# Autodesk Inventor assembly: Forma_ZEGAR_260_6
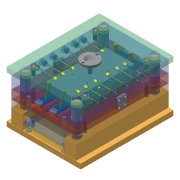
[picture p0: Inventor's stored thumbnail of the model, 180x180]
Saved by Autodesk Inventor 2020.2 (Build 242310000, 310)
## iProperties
Created: 2015-01
Part Number: Forma_ZEGAR_260_6
Document SubType Name: Assembly
Designer: F.Stasiak
Catalog Web Link: www.expertbooks.pl
Manager: www.cadconsulting.pl
Company: Fabian Stasiak CAD Consulting
Author: F.Stasiak
Subject: Zbiór ćwiczeń. Autodesk Inventor 2020. Kurs Professional
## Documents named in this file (14)
- C:\2020_Kurs_Professional\R6 Formy\Forma_ZEGAR_260_6.iam
- C:\2020_Kurs_Professional\R6 Formy\Komponenty\Forma_ZEGAR_260_6_ZEGAR_260_LY.iam
- C:\2020_Kurs_Professional\R6 Formy\Komponenty\Forma_ZEGAR_260_6_RG.ipt
- C:\2020_Kurs_Professional\R6 Formy\Komponenty\Forma_ZEGAR_260_6_CH.ipt
- C:\2020_Kurs_Professional\R6 Formy\Komponenty\MB\DME_E 1\Forma_ZEGAR_260_6_MB.iam
- C:\2020_Kurs_Professional\R6 Formy\Komponenty\Forma_ZEGAR_260_6_Combined CV1.ipt
- C:\2020_Kurs_Professional\R6 Formy\Komponenty\Forma_ZEGAR_260_6_Combined CR1.ipt
- C:\2020_Kurs_Professional\R6 Formy\Komponenty\Wypychacze\DME_AH\Grupa EP2.0\Forma_ZEGAR_260_4_Grupa EP2_EP1.ipt
- C:\2020_Kurs_Professional\R6 Formy\Komponenty\Tuleja wlewowa\DME_AGN\Forma_ZEGAR_260_4_AGN 76-3,5-0.ipt
- C:\2020_Kurs_Professional\R6 Formy\Komponenty\Pierścień centrujący\RABOURDIN_646  typ B\Forma_ZEGAR_260_4_646-90-25-12,5.ipt
- C:\2020_Kurs_Professional\R6 Formy\Komponenty\LS\DME_FW45 1\Forma_ZEGAR_260_6_LS1.iam
- C:\2020_Kurs_Professional\R6 Formy\Komponenty\Komponenty układu chłodzenia\DME_DR 1700\Forma_ZEGAR_260_4_DR 1700 8x2.ipt
- C:\2020_Kurs_Professional\R6 Formy\Komponenty\Komponenty układu chłodzenia\DME_AN\Forma_ZEGAR_260_4_AN-8.ipt
- C:\2020_Kurs_Professional\R6 Formy\Komponenty\Komponenty układu chłodzenia\DME_N (SERIA N 6-1-8 A)\Forma_ZEGAR_260_4_N 6-1-8 A.ipt
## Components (50 placed, 13 different names)
1. Forma_ZEGAR_260_4_ZEGAR_260_LY:1 [sub-assembly] — Równoległy:1, Równoległy:2, Równoległy:3, Równoległy:7, Równoległy:14, Równoległy:15, Równoległy:16, Równoległy:17, Równoległy:18, Równoległy:19, Równoległy:20, Równoległy:21, Równoległy:22, Równoległy:23, Równoległy:24, Równoległy:25, Równoległy:26, Równoległy:27, Równoległy:28, Równoległy:29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
2. Forma_ZEGAR_260_4_RG:1 — Równoległy:4, Równoległy:5, Równoległy:6, Zestawiający:33
3. Forma_ZEGAR_260_4_CH:1
4. Forma_ZEGAR_260_4_MB:1 [sub-assembly] — Równoległy:7, Zestawiający:1, Kąt:1, Równoległy:14, Równoległy:15, Równoległy:16, Równoległy:17, Równoległy:18, Równoległy:19, Równoległy:20, Równoległy:21, Równoległy:22, Równoległy:23, Równoległy:24, Równoległy:25, Równoległy:26, Równoległy:27, Równoległy:28, Równoległy:29, Równoległy:30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
5. Forma_ZEGAR_260_4_Combined CV1:1 — Równoległy:8, Równoległy:9, Równoległy:10, Wstaw:1, Wstaw:2, Wstaw:3, Wstaw:4, Wstaw:5, Wstaw:6, Wstaw:7, Wstaw:8, Wstaw:9, Wstaw:10, Wstaw:11, Wstaw:12, Wstaw:13, Wstaw:14, Wstaw:15, Wstaw:16, Równoległy:201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
6. Forma_ZEGAR_260_4_Combined CR1:1 — Równoległy:11, Równoległy:12, Równoległy:13, Równoległy:204, Równoległy:205, Równoległy:206
7. Forma_ZEGAR_260_4_Grupa EP2_EP1:1 — Zestawiający:2, Kąt:2, Zestawiający:3
8. Forma_ZEGAR_260_4_AGN 76-3,5-0:1 — Zestawiający:32, Zestawiający:33, Zestawiający:35
9. Forma_ZEGAR_260_4_646-90-25-12,5:1 — Zestawiający:34, Zestawiający:35
10. Forma_ZEGAR_260_4_LS1:1 [sub-assembly] — Zestawiający:36, Równoległy:162, Zestawiający:37, Zestawiający:39, Zestawiający:40, Równoległy:163
11. Forma_ZEGAR_260_4_LS1:2 [sub-assembly] — Zestawiający:38, Zestawiający:39, Zestawiający:40, Równoległy:164
12. DR 1700 DR 1700 8x2:1
13. DR 1700 DR 1700 8x2:2
14. DR 1700 DR 1700 8x2:3
15. DR 1700 DR 1700 8x2:4
16. DR 1700 DR 1700 8x2:5
17. DR 1700 DR 1700 8x2:6
18. DR 1700 DR 1700 8x2:7
19. DR 1700 DR 1700 8x2:8
20. DR 1700 DR 1700 8x2:9
21. DR 1700 DR 1700 8x2:10
22. DR 1700 DR 1700 8x2:11
23. DR 1700 DR 1700 8x2:12
24. AN AN-8:1 — Wstaw:1
25. AN AN-8:2 — Wstaw:2
26. AN AN-8:3 — Wstaw:3
27. AN AN-8:4 — Wstaw:4
28. AN AN-8:5 — Wstaw:5
29. AN AN-8:6 — Wstaw:6
30. AN AN-8:7 — Wstaw:7
31. AN AN-8:8 — Wstaw:8
32. AN AN-8:9 — Wstaw:9
33. AN AN-8:10 — Wstaw:10
34. AN AN-8:11 — Wstaw:11
35. AN AN-8:12 — Wstaw:12
36. AN AN-8:13 — Wstaw:13
37. AN AN-8:14 — Wstaw:14
38. AN AN-8:15 — Wstaw:15
39. AN AN-8:16 — Wstaw:16
40. Forma_ZEGAR_260_4_N 6-1-8 A:1 — Wstaw:17
41. Forma_ZEGAR_260_4_N 6-1-8 A:2 — Wstaw:18
42. Forma_ZEGAR_260_4_N 6-1-8 A:3 — Wstaw:19
43. Forma_ZEGAR_260_4_N 6-1-8 A:4 — Wstaw:20
44. Forma_ZEGAR_260_4_N 6-1-8 A:5 — Wstaw:21
45. Forma_ZEGAR_260_4_N 6-1-8 A:6 — Wstaw:22
46. Forma_ZEGAR_260_4_N 6-1-8 A:7 — Wstaw:23
47. Forma_ZEGAR_260_4_N 6-1-8 A:8 — Wstaw:24
48. Forma_ZEGAR_260_4_N 6-1-8 A:9 — Wstaw:25
49. Forma_ZEGAR_260_4_N 6-1-8 A:10 — Wstaw:26
50. Forma_ZEGAR_260_4_N 6-1-8 A:11 — Wstaw:27
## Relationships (247: Flush 190, Mate 28, Insert 27, Angle 2)
- Równoległy:1 [Flush]: Forma_ZEGAR_260_4_ZEGAR_260_LY:1
- Równoległy:2 [Flush]: Forma_ZEGAR_260_4_ZEGAR_260_LY:1
- Równoległy:3 [Flush]: Forma_ZEGAR_260_4_ZEGAR_260_LY:1
- Równoległy:4 [Flush]: Forma_ZEGAR_260_4_RG:1
- Równoległy:5 [Flush]: Forma_ZEGAR_260_4_RG:1
- Równoległy:6 [Flush]: Forma_ZEGAR_260_4_RG:1
- Równoległy:7 [Flush]: Forma_ZEGAR_260_4_ZEGAR_260_LY:1 ↔ Forma_ZEGAR_260_4_MB:1
- Zestawiający:1 [Mate]: Forma_ZEGAR_260_4_MB:1
- Kąt:1 [Angle]: Forma_ZEGAR_260_4_MB:1
- Równoległy:8 [Flush]: Forma_ZEGAR_260_4_Combined CV1:1
- Równoległy:9 [Flush]: Forma_ZEGAR_260_4_Combined CV1:1
- Równoległy:10 [Flush]: Forma_ZEGAR_260_4_Combined CV1:1
- Równoległy:11 [Flush]: Forma_ZEGAR_260_4_Combined CR1:1
- Równoległy:12 [Flush]: Forma_ZEGAR_260_4_Combined CR1:1
- Równoległy:13 [Flush]: Forma_ZEGAR_260_4_Combined CR1:1
- Równoległy:14 [Flush]: Forma_ZEGAR_260_4_ZEGAR_260_LY:1 ↔ Forma_ZEGAR_260_4_MB:1
- Równoległy:15 [Flush]: Forma_ZEGAR_260_4_ZEGAR_260_LY:1 ↔ Forma_ZEGAR_260_4_MB:1
- Równoległy:16 [Flush]: Forma_ZEGAR_260_4_ZEGAR_260_LY:1 ↔ Forma_ZEGAR_260_4_MB:1
- Równoległy:17 [Flush]: Forma_ZEGAR_260_4_ZEGAR_260_LY:1 ↔ Forma_ZEGAR_260_4_MB:1
- Równoległy:18 [Flush]: Forma_ZEGAR_260_4_ZEGAR_260_LY:1 ↔ Forma_ZEGAR_260_4_MB:1
- Równoległy:19 [Flush]: Forma_ZEGAR_260_4_ZEGAR_260_LY:1 ↔ Forma_ZEGAR_260_4_MB:1
- Równoległy:20 [Flush]: Forma_ZEGAR_260_4_ZEGAR_260_LY:1 ↔ Forma_ZEGAR_260_4_MB:1
- Równoległy:21 [Flush]: Forma_ZEGAR_260_4_ZEGAR_260_LY:1 ↔ Forma_ZEGAR_260_4_MB:1
- Równoległy:22 [Flush]: Forma_ZEGAR_260_4_ZEGAR_260_LY:1 ↔ Forma_ZEGAR_260_4_MB:1
- Równoległy:23 [Flush]: Forma_ZEGAR_260_4_ZEGAR_260_LY:1 ↔ Forma_ZEGAR_260_4_MB:1
- Równoległy:24 [Flush]: Forma_ZEGAR_260_4_ZEGAR_260_LY:1 ↔ Forma_ZEGAR_260_4_MB:1
- Równoległy:25 [Flush]: Forma_ZEGAR_260_4_ZEGAR_260_LY:1 ↔ Forma_ZEGAR_260_4_MB:1
- Równoległy:26 [Flush]: Forma_ZEGAR_260_4_ZEGAR_260_LY:1 ↔ Forma_ZEGAR_260_4_MB:1
- Równoległy:27 [Flush]: Forma_ZEGAR_260_4_ZEGAR_260_LY:1 ↔ Forma_ZEGAR_260_4_MB:1
- Równoległy:28 [Flush]: Forma_ZEGAR_260_4_ZEGAR_260_LY:1 ↔ Forma_ZEGAR_260_4_MB:1
- Równoległy:29 [Flush]: Forma_ZEGAR_260_4_ZEGAR_260_LY:1 ↔ Forma_ZEGAR_260_4_MB:1
- Równoległy:30 [Flush]: Forma_ZEGAR_260_4_ZEGAR_260_LY:1 ↔ Forma_ZEGAR_260_4_MB:1
- Równoległy:31 [Flush]: Forma_ZEGAR_260_4_ZEGAR_260_LY:1 ↔ Forma_ZEGAR_260_4_MB:1
- Równoległy:32 [Flush]: Forma_ZEGAR_260_4_ZEGAR_260_LY:1 ↔ Forma_ZEGAR_260_4_MB:1
- Równoległy:33 [Flush]: Forma_ZEGAR_260_4_ZEGAR_260_LY:1 ↔ Forma_ZEGAR_260_4_MB:1
- Równoległy:34 [Flush]: Forma_ZEGAR_260_4_ZEGAR_260_LY:1 ↔ Forma_ZEGAR_260_4_MB:1
- Równoległy:35 [Flush]: Forma_ZEGAR_260_4_ZEGAR_260_LY:1 ↔ Forma_ZEGAR_260_4_MB:1
- Równoległy:36 [Flush]: Forma_ZEGAR_260_4_ZEGAR_260_LY:1 ↔ Forma_ZEGAR_260_4_MB:1
- Równoległy:37 [Flush]: Forma_ZEGAR_260_4_ZEGAR_260_LY:1 ↔ Forma_ZEGAR_260_4_MB:1
- Równoległy:38 [Flush]: Forma_ZEGAR_260_4_ZEGAR_260_LY:1 ↔ Forma_ZEGAR_260_4_MB:1
- Równoległy:39 [Flush]: Forma_ZEGAR_260_4_ZEGAR_260_LY:1 ↔ Forma_ZEGAR_260_4_MB:1
- Równoległy:40 [Flush]: Forma_ZEGAR_260_4_ZEGAR_260_LY:1 ↔ Forma_ZEGAR_260_4_MB:1
- Równoległy:41 [Flush]: Forma_ZEGAR_260_4_ZEGAR_260_LY:1 ↔ Forma_ZEGAR_260_4_MB:1
- Równoległy:42 [Flush]: Forma_ZEGAR_260_4_ZEGAR_260_LY:1 ↔ Forma_ZEGAR_260_4_MB:1
- Równoległy:43 [Flush]: Forma_ZEGAR_260_4_ZEGAR_260_LY:1 ↔ Forma_ZEGAR_260_4_MB:1
- Równoległy:44 [Flush]: Forma_ZEGAR_260_4_ZEGAR_260_LY:1 ↔ Forma_ZEGAR_260_4_MB:1
- Równoległy:45 [Flush]: Forma_ZEGAR_260_4_ZEGAR_260_LY:1 ↔ Forma_ZEGAR_260_4_MB:1
- Równoległy:46 [Flush]: Forma_ZEGAR_260_4_ZEGAR_260_LY:1 ↔ Forma_ZEGAR_260_4_MB:1
- Równoległy:47 [Flush]: Forma_ZEGAR_260_4_ZEGAR_260_LY:1 ↔ Forma_ZEGAR_260_4_MB:1
- Równoległy:48 [Flush]: Forma_ZEGAR_260_4_ZEGAR_260_LY:1 ↔ Forma_ZEGAR_260_4_MB:1
- Równoległy:49 [Flush]: Forma_ZEGAR_260_4_ZEGAR_260_LY:1 ↔ Forma_ZEGAR_260_4_MB:1
- Równoległy:50 [Flush]: Forma_ZEGAR_260_4_ZEGAR_260_LY:1 ↔ Forma_ZEGAR_260_4_MB:1
- Równoległy:51 [Flush]: Forma_ZEGAR_260_4_ZEGAR_260_LY:1 ↔ Forma_ZEGAR_260_4_MB:1
- Równoległy:52 [Flush]: Forma_ZEGAR_260_4_ZEGAR_260_LY:1 ↔ Forma_ZEGAR_260_4_MB:1
- Równoległy:53 [Flush]: Forma_ZEGAR_260_4_ZEGAR_260_LY:1 ↔ Forma_ZEGAR_260_4_MB:1
- Równoległy:54 [Flush]: Forma_ZEGAR_260_4_ZEGAR_260_LY:1 ↔ Forma_ZEGAR_260_4_MB:1
- Równoległy:55 [Flush]: Forma_ZEGAR_260_4_ZEGAR_260_LY:1 ↔ Forma_ZEGAR_260_4_MB:1
- Równoległy:56 [Flush]: Forma_ZEGAR_260_4_ZEGAR_260_LY:1 ↔ Forma_ZEGAR_260_4_MB:1
- Równoległy:57 [Flush]: Forma_ZEGAR_260_4_ZEGAR_260_LY:1 ↔ Forma_ZEGAR_260_4_MB:1
- Równoległy:58 [Flush]: Forma_ZEGAR_260_4_ZEGAR_260_LY:1 ↔ Forma_ZEGAR_260_4_MB:1
- Równoległy:59 [Flush]: Forma_ZEGAR_260_4_ZEGAR_260_LY:1 ↔ Forma_ZEGAR_260_4_MB:1
- Równoległy:60 [Flush]: Forma_ZEGAR_260_4_ZEGAR_260_LY:1 ↔ Forma_ZEGAR_260_4_MB:1
- Równoległy:61 [Flush]: Forma_ZEGAR_260_4_ZEGAR_260_LY:1 ↔ Forma_ZEGAR_260_4_MB:1
- Równoległy:62 [Flush]: Forma_ZEGAR_260_4_ZEGAR_260_LY:1 ↔ Forma_ZEGAR_260_4_MB:1
- Równoległy:63 [Flush]: Forma_ZEGAR_260_4_ZEGAR_260_LY:1 ↔ Forma_ZEGAR_260_4_MB:1
- Równoległy:64 [Flush]: Forma_ZEGAR_260_4_ZEGAR_260_LY:1 ↔ Forma_ZEGAR_260_4_MB:1
- Równoległy:65 [Flush]: Forma_ZEGAR_260_4_ZEGAR_260_LY:1 ↔ Forma_ZEGAR_260_4_MB:1
- Równoległy:66 [Flush]: Forma_ZEGAR_260_4_ZEGAR_260_LY:1 ↔ Forma_ZEGAR_260_4_MB:1
- Równoległy:67 [Flush]: Forma_ZEGAR_260_4_ZEGAR_260_LY:1 ↔ Forma_ZEGAR_260_4_MB:1
- Równoległy:68 [Flush]: Forma_ZEGAR_260_4_ZEGAR_260_LY:1 ↔ Forma_ZEGAR_260_4_MB:1
- Równoległy:69 [Flush]: Forma_ZEGAR_260_4_ZEGAR_260_LY:1 ↔ Forma_ZEGAR_260_4_MB:1
- Równoległy:70 [Flush]: Forma_ZEGAR_260_4_ZEGAR_260_LY:1 ↔ Forma_ZEGAR_260_4_MB:1
- Równoległy:71 [Flush]: Forma_ZEGAR_260_4_ZEGAR_260_LY:1 ↔ Forma_ZEGAR_260_4_MB:1
- Równoległy:72 [Flush]: Forma_ZEGAR_260_4_ZEGAR_260_LY:1 ↔ Forma_ZEGAR_260_4_MB:1
- Równoległy:73 [Flush]: Forma_ZEGAR_260_4_ZEGAR_260_LY:1 ↔ Forma_ZEGAR_260_4_MB:1
- Równoległy:74 [Flush]: Forma_ZEGAR_260_4_ZEGAR_260_LY:1 ↔ Forma_ZEGAR_260_4_MB:1
- Równoległy:75 [Flush]: Forma_ZEGAR_260_4_ZEGAR_260_LY:1 ↔ Forma_ZEGAR_260_4_MB:1
- Równoległy:76 [Flush]: Forma_ZEGAR_260_4_ZEGAR_260_LY:1 ↔ Forma_ZEGAR_260_4_MB:1
- Równoległy:77 [Flush]: Forma_ZEGAR_260_4_ZEGAR_260_LY:1 ↔ Forma_ZEGAR_260_4_MB:1
- Równoległy:78 [Flush]: Forma_ZEGAR_260_4_ZEGAR_260_LY:1 ↔ Forma_ZEGAR_260_4_MB:1
- Równoległy:79 [Flush]: Forma_ZEGAR_260_4_ZEGAR_260_LY:1 ↔ Forma_ZEGAR_260_4_MB:1
- Równoległy:80 [Flush]: Forma_ZEGAR_260_4_ZEGAR_260_LY:1 ↔ Forma_ZEGAR_260_4_MB:1
- Równoległy:81 [Flush]: Forma_ZEGAR_260_4_ZEGAR_260_LY:1 ↔ Forma_ZEGAR_260_4_MB:1
- Równoległy:82 [Flush]: Forma_ZEGAR_260_4_ZEGAR_260_LY:1 ↔ Forma_ZEGAR_260_4_MB:1
- Równoległy:83 [Flush]: Forma_ZEGAR_260_4_ZEGAR_260_LY:1 ↔ Forma_ZEGAR_260_4_MB:1
- Równoległy:84 [Flush]: Forma_ZEGAR_260_4_ZEGAR_260_LY:1 ↔ Forma_ZEGAR_260_4_MB:1
- Równoległy:85 [Flush]: Forma_ZEGAR_260_4_ZEGAR_260_LY:1 ↔ Forma_ZEGAR_260_4_MB:1
- Równoległy:86 [Flush]: Forma_ZEGAR_260_4_ZEGAR_260_LY:1 ↔ Forma_ZEGAR_260_4_MB:1
- Równoległy:87 [Flush]: Forma_ZEGAR_260_4_ZEGAR_260_LY:1 ↔ Forma_ZEGAR_260_4_MB:1
- Równoległy:88 [Flush]: Forma_ZEGAR_260_4_ZEGAR_260_LY:1 ↔ Forma_ZEGAR_260_4_MB:1
- Równoległy:89 [Flush]: Forma_ZEGAR_260_4_ZEGAR_260_LY:1 ↔ Forma_ZEGAR_260_4_MB:1
- Równoległy:90 [Flush]: Forma_ZEGAR_260_4_ZEGAR_260_LY:1 ↔ Forma_ZEGAR_260_4_MB:1
- Równoległy:91 [Flush]: Forma_ZEGAR_260_4_ZEGAR_260_LY:1 ↔ Forma_ZEGAR_260_4_MB:1
- Równoległy:92 [Flush]: Forma_ZEGAR_260_4_ZEGAR_260_LY:1 ↔ Forma_ZEGAR_260_4_MB:1
- Równoległy:93 [Flush]: Forma_ZEGAR_260_4_ZEGAR_260_LY:1 ↔ Forma_ZEGAR_260_4_MB:1
- Równoległy:94 [Flush]: Forma_ZEGAR_260_4_ZEGAR_260_LY:1 ↔ Forma_ZEGAR_260_4_MB:1
- Równoległy:95 [Flush]: Forma_ZEGAR_260_4_ZEGAR_260_LY:1 ↔ Forma_ZEGAR_260_4_MB:1
- Równoległy:96 [Flush]: Forma_ZEGAR_260_4_ZEGAR_260_LY:1 ↔ Forma_ZEGAR_260_4_MB:1
- Równoległy:97 [Flush]: Forma_ZEGAR_260_4_ZEGAR_260_LY:1 ↔ Forma_ZEGAR_260_4_MB:1
- Równoległy:98 [Flush]: Forma_ZEGAR_260_4_ZEGAR_260_LY:1 ↔ Forma_ZEGAR_260_4_MB:1
- Równoległy:99 [Flush]: Forma_ZEGAR_260_4_ZEGAR_260_LY:1 ↔ Forma_ZEGAR_260_4_MB:1
- Równoległy:100 [Flush]: Forma_ZEGAR_260_4_ZEGAR_260_LY:1 ↔ Forma_ZEGAR_260_4_MB:1
- Równoległy:101 [Flush]: Forma_ZEGAR_260_4_ZEGAR_260_LY:1 ↔ Forma_ZEGAR_260_4_MB:1
- Równoległy:102 [Flush]: Forma_ZEGAR_260_4_ZEGAR_260_LY:1 ↔ Forma_ZEGAR_260_4_MB:1
- Równoległy:103 [Flush]: Forma_ZEGAR_260_4_ZEGAR_260_LY:1 ↔ Forma_ZEGAR_260_4_MB:1
- Równoległy:104 [Flush]: Forma_ZEGAR_260_4_ZEGAR_260_LY:1 ↔ Forma_ZEGAR_260_4_MB:1
- Równoległy:105 [Flush]: Forma_ZEGAR_260_4_ZEGAR_260_LY:1 ↔ Forma_ZEGAR_260_4_MB:1
- Równoległy:106 [Flush]: Forma_ZEGAR_260_4_ZEGAR_260_LY:1 ↔ Forma_ZEGAR_260_4_MB:1
- Równoległy:107 [Flush]: Forma_ZEGAR_260_4_ZEGAR_260_LY:1 ↔ Forma_ZEGAR_260_4_MB:1
- Równoległy:108 [Flush]: Forma_ZEGAR_260_4_ZEGAR_260_LY:1 ↔ Forma_ZEGAR_260_4_MB:1
- Równoległy:109 [Flush]: Forma_ZEGAR_260_4_ZEGAR_260_LY:1 ↔ Forma_ZEGAR_260_4_MB:1
- Równoległy:110 [Flush]: Forma_ZEGAR_260_4_ZEGAR_260_LY:1 ↔ Forma_ZEGAR_260_4_MB:1
- Równoległy:111 [Flush]: Forma_ZEGAR_260_4_ZEGAR_260_LY:1 ↔ Forma_ZEGAR_260_4_MB:1
- Równoległy:112 [Flush]: Forma_ZEGAR_260_4_ZEGAR_260_LY:1 ↔ Forma_ZEGAR_260_4_MB:1
- Równoległy:113 [Flush]: Forma_ZEGAR_260_4_ZEGAR_260_LY:1 ↔ Forma_ZEGAR_260_4_MB:1
- Równoległy:114 [Flush]: Forma_ZEGAR_260_4_ZEGAR_260_LY:1 ↔ Forma_ZEGAR_260_4_MB:1
- Równoległy:115 [Flush]: Forma_ZEGAR_260_4_ZEGAR_260_LY:1 ↔ Forma_ZEGAR_260_4_MB:1
- Równoległy:116 [Flush]: Forma_ZEGAR_260_4_ZEGAR_260_LY:1 ↔ Forma_ZEGAR_260_4_MB:1
- Równoległy:117 [Flush]: Forma_ZEGAR_260_4_ZEGAR_260_LY:1 ↔ Forma_ZEGAR_260_4_MB:1
- Równoległy:118 [Flush]: Forma_ZEGAR_260_4_ZEGAR_260_LY:1 ↔ Forma_ZEGAR_260_4_MB:1
- Równoległy:119 [Flush]: Forma_ZEGAR_260_4_ZEGAR_260_LY:1 ↔ Forma_ZEGAR_260_4_MB:1
- Równoległy:120 [Flush]: Forma_ZEGAR_260_4_ZEGAR_260_LY:1 ↔ Forma_ZEGAR_260_4_MB:1
- Równoległy:121 [Flush]: Forma_ZEGAR_260_4_ZEGAR_260_LY:1 ↔ Forma_ZEGAR_260_4_MB:1
- Równoległy:122 [Flush]: Forma_ZEGAR_260_4_ZEGAR_260_LY:1 ↔ Forma_ZEGAR_260_4_MB:1
- Równoległy:123 [Flush]: Forma_ZEGAR_260_4_ZEGAR_260_LY:1 ↔ Forma_ZEGAR_260_4_MB:1
- Równoległy:124 [Flush]: Forma_ZEGAR_260_4_ZEGAR_260_LY:1 ↔ Forma_ZEGAR_260_4_MB:1
- Równoległy:125 [Flush]: Forma_ZEGAR_260_4_ZEGAR_260_LY:1 ↔ Forma_ZEGAR_260_4_MB:1
- Równoległy:126 [Flush]: Forma_ZEGAR_260_4_ZEGAR_260_LY:1 ↔ Forma_ZEGAR_260_4_MB:1
- Równoległy:127 [Flush]: Forma_ZEGAR_260_4_ZEGAR_260_LY:1 ↔ Forma_ZEGAR_260_4_MB:1
- Równoległy:128 [Flush]: Forma_ZEGAR_260_4_ZEGAR_260_LY:1 ↔ Forma_ZEGAR_260_4_MB:1
- Równoległy:129 [Flush]: Forma_ZEGAR_260_4_ZEGAR_260_LY:1 ↔ Forma_ZEGAR_260_4_MB:1
- Równoległy:130 [Flush]: Forma_ZEGAR_260_4_ZEGAR_260_LY:1 ↔ Forma_ZEGAR_260_4_MB:1
- Równoległy:131 [Flush]: Forma_ZEGAR_260_4_ZEGAR_260_LY:1 ↔ Forma_ZEGAR_260_4_MB:1
- Równoległy:132 [Flush]: Forma_ZEGAR_260_4_ZEGAR_260_LY:1 ↔ Forma_ZEGAR_260_4_MB:1
- Równoległy:133 [Flush]: Forma_ZEGAR_260_4_ZEGAR_260_LY:1 ↔ Forma_ZEGAR_260_4_MB:1
- Równoległy:134 [Flush]: Forma_ZEGAR_260_4_ZEGAR_260_LY:1 ↔ Forma_ZEGAR_260_4_MB:1
- Równoległy:135 [Flush]: Forma_ZEGAR_260_4_ZEGAR_260_LY:1 ↔ Forma_ZEGAR_260_4_MB:1
- Równoległy:136 [Flush]: Forma_ZEGAR_260_4_ZEGAR_260_LY:1 ↔ Forma_ZEGAR_260_4_MB:1
- Równoległy:137 [Flush]: Forma_ZEGAR_260_4_ZEGAR_260_LY:1 ↔ Forma_ZEGAR_260_4_MB:1
- Równoległy:138 [Flush]: Forma_ZEGAR_260_4_ZEGAR_260_LY:1 ↔ Forma_ZEGAR_260_4_MB:1
- Równoległy:139 [Flush]: Forma_ZEGAR_260_4_ZEGAR_260_LY:1 ↔ Forma_ZEGAR_260_4_MB:1
- Równoległy:140 [Flush]: Forma_ZEGAR_260_4_ZEGAR_260_LY:1 ↔ Forma_ZEGAR_260_4_MB:1
- Równoległy:141 [Flush]: Forma_ZEGAR_260_4_ZEGAR_260_LY:1 ↔ Forma_ZEGAR_260_4_MB:1
- Równoległy:142 [Flush]: Forma_ZEGAR_260_4_ZEGAR_260_LY:1 ↔ Forma_ZEGAR_260_4_MB:1
- Równoległy:143 [Flush]: Forma_ZEGAR_260_4_ZEGAR_260_LY:1 ↔ Forma_ZEGAR_260_4_MB:1
- Równoległy:144 [Flush]: Forma_ZEGAR_260_4_ZEGAR_260_LY:1 ↔ Forma_ZEGAR_260_4_MB:1
- Równoległy:145 [Flush]: Forma_ZEGAR_260_4_ZEGAR_260_LY:1 ↔ Forma_ZEGAR_260_4_MB:1
- Zestawiający:2 [Mate]: Forma_ZEGAR_260_4_Grupa EP2_EP1:1
- Kąt:2 [Angle]: Forma_ZEGAR_260_4_Grupa EP2_EP1:1
- Zestawiający:3 [Mate]: Forma_ZEGAR_260_4_MB:1 ↔ Forma_ZEGAR_260_4_Grupa EP2_EP1:1
- Zestawiający:16 [Mate]: Forma_ZEGAR_260_4_ZEGAR_260_LY:1 ↔ Forma_ZEGAR_260_4_MB:1
- Równoległy:150 [Flush]: Forma_ZEGAR_260_4_ZEGAR_260_LY:1 ↔ Forma_ZEGAR_260_4_MB:1
- Równoległy:151 [Flush]: Forma_ZEGAR_260_4_ZEGAR_260_LY:1 ↔ Forma_ZEGAR_260_4_MB:1
- Zestawiający:17 [Mate]: Forma_ZEGAR_260_4_ZEGAR_260_LY:1 ↔ Forma_ZEGAR_260_4_MB:1
- Równoległy:152 [Flush]: Forma_ZEGAR_260_4_ZEGAR_260_LY:1 ↔ Forma_ZEGAR_260_4_MB:1
- Równoległy:153 [Flush]: Forma_ZEGAR_260_4_ZEGAR_260_LY:1 ↔ Forma_ZEGAR_260_4_MB:1
- Zestawiający:18 [Mate]: Forma_ZEGAR_260_4_ZEGAR_260_LY:1 ↔ Forma_ZEGAR_260_4_MB:1
- Równoległy:154 [Flush]: Forma_ZEGAR_260_4_ZEGAR_260_LY:1 ↔ Forma_ZEGAR_260_4_MB:1
- Równoległy:155 [Flush]: Forma_ZEGAR_260_4_ZEGAR_260_LY:1 ↔ Forma_ZEGAR_260_4_MB:1
- Zestawiający:19 [Mate]: Forma_ZEGAR_260_4_ZEGAR_260_LY:1 ↔ Forma_ZEGAR_260_4_MB:1
- Równoległy:156 [Flush]: Forma_ZEGAR_260_4_ZEGAR_260_LY:1 ↔ Forma_ZEGAR_260_4_MB:1
- Równoległy:157 [Flush]: Forma_ZEGAR_260_4_ZEGAR_260_LY:1 ↔ Forma_ZEGAR_260_4_MB:1
- Zestawiający:20 [Mate]: Forma_ZEGAR_260_4_ZEGAR_260_LY:1 ↔ Forma_ZEGAR_260_4_MB:1
- Równoległy:158 [Flush]: Forma_ZEGAR_260_4_ZEGAR_260_LY:1 ↔ Forma_ZEGAR_260_4_MB:1
- Zestawiający:21 [Mate]: Forma_ZEGAR_260_4_ZEGAR_260_LY:1 ↔ Forma_ZEGAR_260_4_MB:1
- Zestawiający:22 [Mate]: Forma_ZEGAR_260_4_ZEGAR_260_LY:1 ↔ Forma_ZEGAR_260_4_MB:1
- Zestawiający:23 [Mate]: Forma_ZEGAR_260_4_ZEGAR_260_LY:1 ↔ Forma_ZEGAR_260_4_MB:1
- Równoległy:159 [Flush]: Forma_ZEGAR_260_4_ZEGAR_260_LY:1 ↔ Forma_ZEGAR_260_4_MB:1
- Zestawiający:24 [Mate]: Forma_ZEGAR_260_4_ZEGAR_260_LY:1 ↔ Forma_ZEGAR_260_4_MB:1
- Zestawiający:25 [Mate]: Forma_ZEGAR_260_4_ZEGAR_260_LY:1 ↔ Forma_ZEGAR_260_4_MB:1
- Zestawiający:26 [Mate]: Forma_ZEGAR_260_4_ZEGAR_260_LY:1 ↔ Forma_ZEGAR_260_4_MB:1
- Równoległy:160 [Flush]: Forma_ZEGAR_260_4_ZEGAR_260_LY:1 ↔ Forma_ZEGAR_260_4_MB:1
- Zestawiający:27 [Mate]: Forma_ZEGAR_260_4_ZEGAR_260_LY:1 ↔ Forma_ZEGAR_260_4_MB:1
- Zestawiający:28 [Mate]: Forma_ZEGAR_260_4_ZEGAR_260_LY:1 ↔ Forma_ZEGAR_260_4_MB:1
- Zestawiający:29 [Mate]: Forma_ZEGAR_260_4_ZEGAR_260_LY:1 ↔ Forma_ZEGAR_260_4_MB:1
- Równoległy:161 [Flush]: Forma_ZEGAR_260_4_ZEGAR_260_LY:1 ↔ Forma_ZEGAR_260_4_MB:1
- Zestawiający:30 [Mate]: Forma_ZEGAR_260_4_ZEGAR_260_LY:1 ↔ Forma_ZEGAR_260_4_MB:1
- Zestawiający:31 [Mate]: Forma_ZEGAR_260_4_ZEGAR_260_LY:1 ↔ Forma_ZEGAR_260_4_MB:1
- Zestawiający:32 [Mate]: Forma_ZEGAR_260_4_MB:1 ↔ Forma_ZEGAR_260_4_AGN 76-3,5-0:1
- Zestawiający:33 [Mate]: Forma_ZEGAR_260_4_RG:1 ↔ Forma_ZEGAR_260_4_AGN 76-3,5-0:1
- Zestawiający:34 [Mate]: Forma_ZEGAR_260_4_MB:1 ↔ Forma_ZEGAR_260_4_646-90-25-12,5:1
- Zestawiający:35 [Mate]: Forma_ZEGAR_260_4_AGN 76-3,5-0:1 ↔ Forma_ZEGAR_260_4_646-90-25-12,5:1
- Zestawiający:36 [Mate]: Forma_ZEGAR_260_4_MB:1 ↔ Forma_ZEGAR_260_4_LS1:1
- Równoległy:162 [Flush]: Forma_ZEGAR_260_4_MB:1 ↔ Forma_ZEGAR_260_4_LS1:1
- Zestawiający:37 [Mate]: Forma_ZEGAR_260_4_LS1:1
- Zestawiający:38 [Mate]: Forma_ZEGAR_260_4_MB:1 ↔ Forma_ZEGAR_260_4_LS1:2
- Zestawiający:39 [Mate]: Forma_ZEGAR_260_4_LS1:1 ↔ Forma_ZEGAR_260_4_LS1:2
- Zestawiający:40 [Mate]: Forma_ZEGAR_260_4_LS1:1 ↔ Forma_ZEGAR_260_4_LS1:2
- Równoległy:163 [Flush]: Forma_ZEGAR_260_4_MB:1 ↔ Forma_ZEGAR_260_4_LS1:1
- Równoległy:164 [Flush]: Forma_ZEGAR_260_4_MB:1 ↔ Forma_ZEGAR_260_4_LS1:2
- Wstaw:1 [Insert]: Forma_ZEGAR_260_4_Combined CV1:1 ↔ AN AN-8:1
- Wstaw:2 [Insert]: Forma_ZEGAR_260_4_Combined CV1:1 ↔ AN AN-8:2
- Wstaw:3 [Insert]: Forma_ZEGAR_260_4_Combined CV1:1 ↔ AN AN-8:3
- Wstaw:4 [Insert]: Forma_ZEGAR_260_4_Combined CV1:1 ↔ AN AN-8:4
- Wstaw:5 [Insert]: Forma_ZEGAR_260_4_Combined CV1:1 ↔ AN AN-8:5
- Wstaw:6 [Insert]: Forma_ZEGAR_260_4_Combined CV1:1 ↔ AN AN-8:6
- Wstaw:7 [Insert]: Forma_ZEGAR_260_4_Combined CV1:1 ↔ AN AN-8:7
- Wstaw:8 [Insert]: Forma_ZEGAR_260_4_Combined CV1:1 ↔ AN AN-8:8
- Wstaw:9 [Insert]: Forma_ZEGAR_260_4_Combined CV1:1 ↔ AN AN-8:9
- Wstaw:10 [Insert]: Forma_ZEGAR_260_4_Combined CV1:1 ↔ AN AN-8:10
- Wstaw:11 [Insert]: Forma_ZEGAR_260_4_Combined CV1:1 ↔ AN AN-8:11
- Wstaw:12 [Insert]: Forma_ZEGAR_260_4_Combined CV1:1 ↔ AN AN-8:12
- Wstaw:13 [Insert]: Forma_ZEGAR_260_4_Combined CV1:1 ↔ AN AN-8:13
- Wstaw:14 [Insert]: Forma_ZEGAR_260_4_Combined CV1:1 ↔ AN AN-8:14
- Wstaw:15 [Insert]: Forma_ZEGAR_260_4_Combined CV1:1 ↔ AN AN-8:15
- Wstaw:16 [Insert]: Forma_ZEGAR_260_4_Combined CV1:1 ↔ AN AN-8:16
- Wstaw:17 [Insert]: Forma_ZEGAR_260_4_MB:1 ↔ Forma_ZEGAR_260_4_N 6-1-8 A:1
- Wstaw:18 [Insert]: Forma_ZEGAR_260_4_MB:1 ↔ Forma_ZEGAR_260_4_N 6-1-8 A:2
- Wstaw:19 [Insert]: Forma_ZEGAR_260_4_MB:1 ↔ Forma_ZEGAR_260_4_N 6-1-8 A:3
- Wstaw:20 [Insert]: Forma_ZEGAR_260_4_MB:1 ↔ Forma_ZEGAR_260_4_N 6-1-8 A:4
- Wstaw:21 [Insert]: Forma_ZEGAR_260_4_MB:1 ↔ Forma_ZEGAR_260_4_N 6-1-8 A:5
- Wstaw:22 [Insert]: Forma_ZEGAR_260_4_MB:1 ↔ Forma_ZEGAR_260_4_N 6-1-8 A:6
- Wstaw:23 [Insert]: Forma_ZEGAR_260_4_MB:1 ↔ Forma_ZEGAR_260_4_N 6-1-8 A:7
- Wstaw:24 [Insert]: Forma_ZEGAR_260_4_MB:1 ↔ Forma_ZEGAR_260_4_N 6-1-8 A:8
- Wstaw:25 [Insert]: Forma_ZEGAR_260_4_MB:1 ↔ Forma_ZEGAR_260_4_N 6-1-8 A:9
- Wstaw:26 [Insert]: Forma_ZEGAR_260_4_MB:1 ↔ Forma_ZEGAR_260_4_N 6-1-8 A:10
- Wstaw:27 [Insert]: Forma_ZEGAR_260_4_MB:1 ↔ Forma_ZEGAR_260_4_N 6-1-8 A:11
- Równoległy:177 [Flush]: Forma_ZEGAR_260_4_ZEGAR_260_LY:1 ↔ Forma_ZEGAR_260_4_MB:1
- Równoległy:178 [Flush]: Forma_ZEGAR_260_4_ZEGAR_260_LY:1 ↔ Forma_ZEGAR_260_4_MB:1
- Równoległy:179 [Flush]: Forma_ZEGAR_260_4_ZEGAR_260_LY:1 ↔ Forma_ZEGAR_260_4_MB:1
- Równoległy:180 [Flush]: Forma_ZEGAR_260_4_ZEGAR_260_LY:1 ↔ Forma_ZEGAR_260_4_MB:1
- Równoległy:181 [Flush]: Forma_ZEGAR_260_4_ZEGAR_260_LY:1 ↔ Forma_ZEGAR_260_4_MB:1
- Równoległy:182 [Flush]: Forma_ZEGAR_260_4_ZEGAR_260_LY:1 ↔ Forma_ZEGAR_260_4_MB:1
- Równoległy:183 [Flush]: Forma_ZEGAR_260_4_ZEGAR_260_LY:1 ↔ Forma_ZEGAR_260_4_MB:1
- Równoległy:184 [Flush]: Forma_ZEGAR_260_4_ZEGAR_260_LY:1 ↔ Forma_ZEGAR_260_4_MB:1
- Równoległy:185 [Flush]: Forma_ZEGAR_260_4_ZEGAR_260_LY:1 ↔ Forma_ZEGAR_260_4_MB:1
- Równoległy:186 [Flush]: Forma_ZEGAR_260_4_ZEGAR_260_LY:1 ↔ Forma_ZEGAR_260_4_MB:1
- Równoległy:187 [Flush]: Forma_ZEGAR_260_4_ZEGAR_260_LY:1 ↔ Forma_ZEGAR_260_4_MB:1
- Równoległy:188 [Flush]: Forma_ZEGAR_260_4_ZEGAR_260_LY:1 ↔ Forma_ZEGAR_260_4_MB:1
- Równoległy:189 [Flush]: Forma_ZEGAR_260_4_ZEGAR_260_LY:1 ↔ Forma_ZEGAR_260_4_MB:1
- Równoległy:190 [Flush]: Forma_ZEGAR_260_4_ZEGAR_260_LY:1 ↔ Forma_ZEGAR_260_4_MB:1
- Równoległy:191 [Flush]: Forma_ZEGAR_260_4_ZEGAR_260_LY:1 ↔ Forma_ZEGAR_260_4_MB:1
- Równoległy:192 [Flush]: Forma_ZEGAR_260_4_ZEGAR_260_LY:1 ↔ Forma_ZEGAR_260_4_MB:1
- Równoległy:193 [Flush]: Forma_ZEGAR_260_4_ZEGAR_260_LY:1 ↔ Forma_ZEGAR_260_4_MB:1
- Równoległy:194 [Flush]: Forma_ZEGAR_260_4_ZEGAR_260_LY:1 ↔ Forma_ZEGAR_260_4_MB:1
- Równoległy:195 [Flush]: Forma_ZEGAR_260_4_ZEGAR_260_LY:1 ↔ Forma_ZEGAR_260_4_MB:1
- Równoległy:196 [Flush]: Forma_ZEGAR_260_4_ZEGAR_260_LY:1 ↔ Forma_ZEGAR_260_4_MB:1
- Równoległy:197 [Flush]: Forma_ZEGAR_260_4_ZEGAR_260_LY:1 ↔ Forma_ZEGAR_260_4_MB:1
- Równoległy:198 [Flush]: Forma_ZEGAR_260_4_ZEGAR_260_LY:1 ↔ Forma_ZEGAR_260_4_MB:1
- Równoległy:199 [Flush]: Forma_ZEGAR_260_4_ZEGAR_260_LY:1 ↔ Forma_ZEGAR_260_4_MB:1
- Równoległy:200 [Flush]: Forma_ZEGAR_260_4_ZEGAR_260_LY:1 ↔ Forma_ZEGAR_260_4_MB:1
- Równoległy:201 [Flush]: Forma_ZEGAR_260_4_MB:1 ↔ Forma_ZEGAR_260_4_Combined CV1:1
- Równoległy:202 [Flush]: Forma_ZEGAR_260_4_MB:1 ↔ Forma_ZEGAR_260_4_Combined CV1:1
- Równoległy:203 [Flush]: Forma_ZEGAR_260_4_MB:1 ↔ Forma_ZEGAR_260_4_Combined CV1:1
- Równoległy:204 [Flush]: Forma_ZEGAR_260_4_MB:1 ↔ Forma_ZEGAR_260_4_Combined CR1:1
- Równoległy:205 [Flush]: Forma_ZEGAR_260_4_MB:1 ↔ Forma_ZEGAR_260_4_Combined CR1:1
- Równoległy:206 [Flush]: Forma_ZEGAR_260_4_MB:1 ↔ Forma_ZEGAR_260_4_Combined CR1:1
